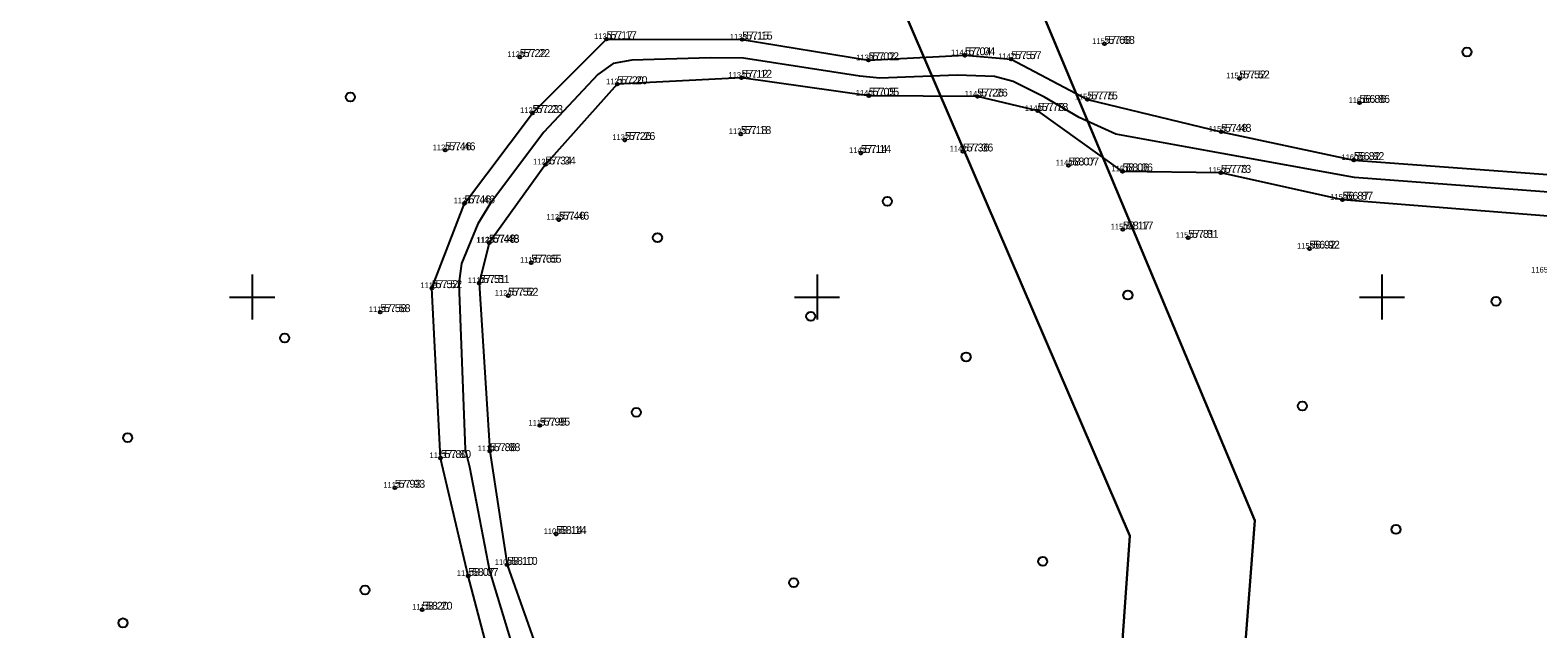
# Model space of a CAD drawing. Extents: x 554846 to 556995, y 6445875 to 6446723.
# Drawn here: x 555130.4 to 555263.8, y 6446120.7 to 6446173.6 of the extents above; entities that cross this region are included whole.
import ezdxf

# ---------------------------------------------------------------- set-up
doc = ezdxf.new("R2010")
doc.units = 0
for name, color, linetype in [('HALJASTUS', 7, 'Continuous'), ('KORGUS-EH2000', 7, 'Continuous'), ('MOOTKORG-EH2000', 7, 'Continuous'), ('MOOTMPUNKT', 7, 'Continuous'), ('MOOTNR', 7, 'Continuous'), ('PIIR', 7, 'Continuous'), ('TEE', 7, 'Continuous'), ('VORK', 7, 'Continuous')]:
    doc.layers.add(name, color=color, linetype=linetype)

msp = doc.modelspace()

# ---------------------------------------------------------------- linework, layer by layer
at = {"layer": 'HALJASTUS'}
for centre in [(555257.52, 6446171.69), (555158.7, 6446167.7), (555206.23, 6446158.47), (555185.88, 6446155.26), (555227.51, 6446150.17), (555260.1, 6446149.61), (555199.45, 6446148.29), (555152.89, 6446146.38), (555213.2, 6446144.71), (555242.96, 6446140.37), (555184, 6446139.81), (555138.98, 6446137.55), (555251.25, 6446129.44), (555219.98, 6446126.61), (555197.94, 6446124.73), (555160, 6446124.08), (555138.57, 6446121.18)]:
    msp.add_circle(centre, 0.4, dxfattribs=at)
at = {"layer": 'KORGUS-EH2000'}
for centre in [(555181.37, 6446172.82), (555193.38, 6446172.78), (555173.69, 6446171.23), (555213.08, 6446171.39), (555225.44, 6446172.4), (555204.57, 6446170.95), (555217.18, 6446171.05), (555182.31, 6446168.83), (555193.33, 6446169.4), (555237.38, 6446169.34), (555204.58, 6446167.81), (555214.19, 6446167.74), (555223.94, 6446167.48), (555248.02, 6446167.18), (555174.82, 6446166.28), (555219.55, 6446166.47), (555235.76, 6446164.62), (555183, 6446163.9), (555193.26, 6446164.42), (555167.08, 6446162.99), (555203.87, 6446162.75), (555212.91, 6446162.88), (555247.52, 6446162.12), (555175.96, 6446161.73), (555222.27, 6446161.64), (555227.04, 6446161.12), (555235.74, 6446160.99), (555168.81, 6446158.29), (555246.52, 6446158.61), (555177.15, 6446156.85), (555227.08, 6446155.98), (555232.85, 6446155.24), (555170.97, 6446154.8), (555170.97, 6446154.83), (555243.58, 6446154.28), (555174.7, 6446153.04), (555170.1, 6446151.24), (555165.9, 6446150.79), (555172.65, 6446150.12), (555161.33, 6446148.67), (555175.46, 6446138.63), (555166.69, 6446135.76), (555171.05, 6446136.37), (555162.63, 6446133.13), (555176.91, 6446129.04), (555172.58, 6446126.31), (555169.12, 6446125.33), (555165.05, 6446122.34)]:
    msp.add_circle(centre, 0.125, dxfattribs=at)
at = {"layer": 'MOOTMPUNKT'}
for centre in [(555181.37, 6446172.82), (555193.38, 6446172.78), (555173.69, 6446171.23), (555213.08, 6446171.39), (555225.44, 6446172.4), (555204.57, 6446170.95), (555217.18, 6446171.05), (555182.31, 6446168.83), (555193.33, 6446169.4), (555237.38, 6446169.34), (555204.58, 6446167.81), (555214.19, 6446167.74), (555223.94, 6446167.48), (555248.02, 6446167.18), (555174.82, 6446166.28), (555219.55, 6446166.47), (555235.76, 6446164.62), (555183, 6446163.9), (555193.26, 6446164.42), (555167.08, 6446162.99), (555203.87, 6446162.75), (555212.91, 6446162.88), (555247.52, 6446162.12), (555175.96, 6446161.73), (555222.27, 6446161.64), (555227.04, 6446161.12), (555235.74, 6446160.99), (555168.81, 6446158.29), (555246.52, 6446158.61), (555177.15, 6446156.85), (555227.08, 6446155.98), (555232.85, 6446155.24), (555170.97, 6446154.8), (555170.97, 6446154.83), (555243.58, 6446154.28), (555174.7, 6446153.04), (555170.1, 6446151.24), (555165.9, 6446150.79), (555172.65, 6446150.12), (555161.33, 6446148.67), (555175.46, 6446138.63), (555166.69, 6446135.76), (555171.05, 6446136.37), (555162.63, 6446133.13), (555176.91, 6446129.04), (555172.58, 6446126.31), (555169.12, 6446125.33), (555165.05, 6446122.34)]:
    msp.add_circle(centre, 0.125, dxfattribs=at)
at = {"layer": 'PIIR'}
msp.add_lwpolyline([(555289.66, 6445948.39), (555259.76, 6445985.47), (555217.2, 6446027.3), (555221.59, 6446040.5), (555235.83, 6446092.25), (555238.76, 6446130.23), (555175.25, 6446281.89), (555176.83, 6446322.12), (555182.27, 6446354.13), (555578.67, 6446397.08)], dxfattribs=at)
for points in [[(555217.2, 6446027.3), (555207.97, 6446036.37), (555211.87, 6446046.6), (555225.2, 6446093.61), (555227.69, 6446128.87), (555162.59, 6446280.08), (555164.63, 6446323.25), (555170.51, 6446352.86), (555182.27, 6446354.13), (555176.83, 6446322.12), (555175.25, 6446281.89), (555238.76, 6446130.23), (555235.83, 6446092.25), (555221.59, 6446040.5)], [(554929.82, 6446275.15), (554900.05, 6446303.23), (554899.45, 6446307.62), (554900.2, 6446312.5), (554902.6, 6446318.8), (554905.25, 6446321.45), (555070.62, 6446339.03), (555070.32, 6446342.01), (555170.51, 6446352.86), (555164.63, 6446323.25), (555162.59, 6446280.08), (555227.69, 6446128.87), (555225.2, 6446093.61), (555211.87, 6446046.6), (555207.97, 6446036.37), (555171.51, 6446072.2), (555063.52, 6446162.84), (555018.2, 6446200.67), (554979.69, 6446232.72)]]:
    msp.add_lwpolyline(points, close=True, dxfattribs=at)
at = {"layer": 'TEE'}
for points in [[(555172.22, 6446113.57), (555169.12, 6446125.33), (555166.69, 6446135.76), (555165.9, 6446150.79), (555168.81, 6446158.29), (555174.82, 6446166.28), (555181.37, 6446172.82), (555193.38, 6446172.78), (555204.57, 6446170.95), (555213.08, 6446171.39), (555217.18, 6446171.05), (555223.94, 6446167.48), (555235.76, 6446164.62), (555247.52, 6446162.12), (555265.47, 6446160.79)], [(555265.92, 6446159.2), (555247.57, 6446160.59), (555235.87, 6446162.7), (555226.44, 6446164.4), (555223.2, 6446165.88), (555220.13, 6446167.68), (555217.35, 6446169.06), (555215.7, 6446169.52), (555212.39, 6446169.64), (555205.55, 6446169.35), (555203.8, 6446169.53), (555193.5, 6446171.13), (555190.57, 6446171.15), (555183.62, 6446170.96), (555181.97, 6446170.67), (555180.61, 6446169.68), (555175.83, 6446164.59), (555171.11, 6446158.31), (555169.97, 6446156.48), (555168.52, 6446152.96), (555168.3, 6446151.2), (555168.69, 6446141.15), (555168.87, 6446136.51), (555169.25, 6446134.98), (555171.02, 6446125.77), (555174.13, 6446115.49)], [(555265.44, 6446157.09), (555246.52, 6446158.61), (555235.74, 6446160.99), (555227.04, 6446161.12), (555219.55, 6446166.47), (555214.19, 6446167.74), (555204.58, 6446167.81), (555193.33, 6446169.4), (555182.31, 6446168.83), (555175.96, 6446161.73), (555170.97, 6446154.8), (555170.1, 6446151.24), (555171.05, 6446136.37), (555172.58, 6446126.31), (555176.28, 6446115.8)]]:
    msp.add_lwpolyline(points, dxfattribs=at)
at = {"layer": 'VORK'}
for p, q in [((555150, 6446152), (555150, 6446148)), ((555200, 6446152), (555200, 6446148)), ((555250, 6446152), (555250, 6446148)), ((555148, 6446150), (555152, 6446150)), ((555198, 6446150), (555202, 6446150)), ((555248, 6446150), (555252, 6446150))]:
    msp.add_line(p, q, dxfattribs=at)

# ---------------------------------------------------------------- texts
at = {"layer": 'KORGUS-EH2000'}
for s, p in [('57.17', (555181.72, 6446172.82)), ('57.15', (555193.73, 6446172.78)), ('57.68', (555225.79, 6446172.4)), ('57.22', (555174.04, 6446171.23)), ('57.02', (555204.92, 6446170.95)), ('57.04', (555213.43, 6446171.39)), ('57.57', (555217.53, 6446171.05)), ('57.12', (555193.68, 6446169.4)), ('57.52', (555237.73, 6446169.34)), ('57.20', (555182.66, 6446168.83)), ('57.05', (555204.93, 6446167.81)), ('57.26', (555214.54, 6446167.74)), ('57.75', (555224.29, 6446167.48)), ('56.86', (555248.37, 6446167.18)), ('57.23', (555175.17, 6446166.28)), ('57.78', (555219.9, 6446166.47)), ('57.26', (555183.35, 6446163.9)), ('57.18', (555193.61, 6446164.42)), ('57.48', (555236.11, 6446164.62)), ('57.46', (555167.43, 6446162.99)), ('57.14', (555204.22, 6446162.75)), ('57.36', (555213.26, 6446162.88)), ('57.34', (555176.31, 6446161.73)), ('58.07', (555222.62, 6446161.64)), ('56.82', (555247.87, 6446162.12)), ('58.06', (555227.39, 6446161.12)), ('57.73', (555236.09, 6446160.99)), ('56.87', (555246.87, 6446158.61)), ('57.46', (555169.16, 6446158.29)), ('57.46', (555177.5, 6446156.85)), ('58.17', (555227.43, 6446155.98)), ('57.48', (555171.32, 6446154.83)), ('57.48', (555171.32, 6446154.8)), ('57.81', (555233.2, 6446155.24)), ('56.92', (555243.93, 6446154.28)), ('57.65', (555175.05, 6446153.04)), ('57.52', (555166.25, 6446150.79)), ('57.51', (555170.45, 6446151.24)), ('57.52', (555173, 6446150.12)), ('57.58', (555161.68, 6446148.67)), ('57.95', (555175.81, 6446138.63)), ('57.88', (555171.4, 6446136.37)), ('57.80', (555167.04, 6446135.76)), ('57.93', (555162.98, 6446133.13)), ('58.14', (555177.26, 6446129.04)), ('58.07', (555169.47, 6446125.33)), ('58.10', (555172.93, 6446126.31)), ('58.20', (555165.4, 6446122.34))]:
    msp.add_text(s, height=0.7, dxfattribs=at).set_placement(p)
at = {"layer": 'MOOTKORG-EH2000'}
for s, p in [('57.17', (555181.37, 6446172.82)), ('57.15', (555193.38, 6446172.78)), ('57.68', (555225.44, 6446172.4)), ('57.22', (555173.69, 6446171.23)), ('57.02', (555204.57, 6446170.95)), ('57.04', (555213.08, 6446171.39)), ('57.57', (555217.18, 6446171.05)), ('57.12', (555193.33, 6446169.4)), ('57.52', (555237.38, 6446169.34)), ('57.20', (555182.31, 6446168.83)), ('57.05', (555204.58, 6446167.81)), ('57.26', (555214.19, 6446167.74)), ('57.75', (555223.94, 6446167.48)), ('56.86', (555248.02, 6446167.18)), ('57.23', (555174.82, 6446166.28)), ('57.78', (555219.55, 6446166.47)), ('57.26', (555183, 6446163.9)), ('57.18', (555193.26, 6446164.42)), ('57.48', (555235.76, 6446164.62)), ('57.46', (555167.08, 6446162.99)), ('57.14', (555203.87, 6446162.75)), ('57.36', (555212.91, 6446162.88)), ('57.34', (555175.96, 6446161.73)), ('58.07', (555222.27, 6446161.64)), ('56.82', (555247.52, 6446162.12)), ('58.06', (555227.04, 6446161.12)), ('57.73', (555235.74, 6446160.99)), ('56.87', (555246.52, 6446158.61)), ('57.46', (555168.81, 6446158.29)), ('57.46', (555177.15, 6446156.85)), ('58.17', (555227.08, 6446155.98)), ('57.48', (555170.97, 6446154.83)), ('57.48', (555170.97, 6446154.8)), ('57.81', (555232.85, 6446155.24)), ('56.92', (555243.58, 6446154.28)), ('57.65', (555174.7, 6446153.04)), ('57.52', (555165.9, 6446150.79)), ('57.51', (555170.1, 6446151.24)), ('57.52', (555172.65, 6446150.12)), ('57.58', (555161.33, 6446148.67)), ('57.95', (555175.46, 6446138.63)), ('57.88', (555171.05, 6446136.37)), ('57.80', (555166.69, 6446135.76)), ('57.93', (555162.63, 6446133.13)), ('58.14', (555176.91, 6446129.04)), ('58.07', (555169.12, 6446125.33)), ('58.10', (555172.58, 6446126.31)), ('58.20', (555165.05, 6446122.34))]:
    msp.add_text(s, height=0.7, dxfattribs=at).set_placement(p)
at = {"layer": 'MOOTNR'}
for s, p in [('1130', (555180.27, 6446172.82)), ('1135', (555192.28, 6446172.78)), ('1153', (555224.36, 6446172.4)), ('1128', (555172.59, 6446171.23)), ('1139', (555203.47, 6446170.95)), ('1144', (555211.86, 6446171.39)), ('1147', (555216.03, 6446171.05)), ('1131', (555181.33, 6446168.83)), ('1134', (555192.16, 6446169.4)), ('1154', (555236.21, 6446169.34)), ('1140', (555203.43, 6446167.81)), ('1143', (555213.07, 6446167.74)), ('1152', (555222.81, 6446167.48)), ('1161', (555247.05, 6446167.18)), ('1127', (555173.72, 6446166.28)), ('1148', (555218.4, 6446166.47)), ('1133', (555192.19, 6446164.42)), ('1155', (555234.66, 6446164.62)), ('1120', (555165.98, 6446162.99)), ('1132', (555181.88, 6446163.9)), ('1142', (555211.74, 6446162.88)), ('1126', (555174.86, 6446161.73)), ('1141', (555202.84, 6446162.75)), ('1149', (555221.12, 6446161.64)), ('1160', (555246.42, 6446162.12)), ('1151', (555226.07, 6446161.12)), ('1156', (555234.64, 6446160.99)), ('1121', (555167.84, 6446158.29)), ('1159', (555245.42, 6446158.61)), ('1125', (555176.05, 6446156.85)), ('1122', (555169.84, 6446154.8)), ('1123', (555169.9, 6446154.83)), ('1150', (555225.99, 6446155.98)), ('1157', (555231.75, 6446155.24)), ('1158', (555242.48, 6446154.28)), ('1116', (555173.71, 6446153.04)), ('1165', (555263.21, 6446152.17)), ('1118', (555164.9, 6446150.79)), ('1117', (555169.1, 6446151.24)), ('1124', (555171.48, 6446150.12)), ('1119', (555160.33, 6446148.67)), ('1115', (555174.46, 6446138.63)), ('1114', (555169.97, 6446136.37)), ('1113', (555165.71, 6446135.76)), ('1112', (555161.61, 6446133.13)), ('1108', (555175.81, 6446129.04)), ('1109', (555171.48, 6446126.31)), ('1110', (555168.12, 6446125.33)), ('1111', (555164.17, 6446122.34))]:
    msp.add_text(s, height=0.5, dxfattribs=at).set_placement(p)

doc.saveas('drawing.dxf')
